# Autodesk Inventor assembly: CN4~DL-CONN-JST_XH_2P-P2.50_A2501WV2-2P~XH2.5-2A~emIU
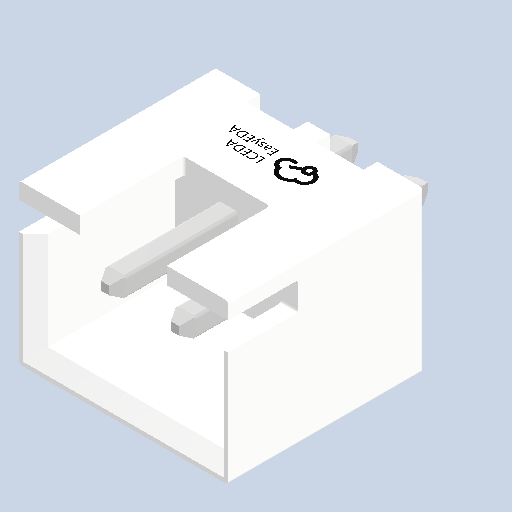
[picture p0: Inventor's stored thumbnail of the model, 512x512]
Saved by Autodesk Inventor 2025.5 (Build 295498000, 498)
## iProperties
Created: 2026-10
Part Number: CN4~DL-CONN-JST_XH_2P-P2.50_A2501WV2-2P~XH2.5-2A~emIU
Document SubType Name: Assembly
Designer: Luis M
Author: Luis M
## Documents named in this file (2)
- C:\Users\Luis M\Downloads\3D_PCB1_2026-10-28\CN4~DL-CONN-JST_XH_2P-P2.50_A2501WV2-2P~XH2.5-2A~emIU.iam
- C:\Users\Luis M\Downloads\3D_PCB1_2026-10-28\DL-CONN-JST_XH_2P-P2.50_A2501WV2-2P~XH2.5-2A~i7Qw.ipt
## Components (1 placed, 1 different names)
1. CN4->0
